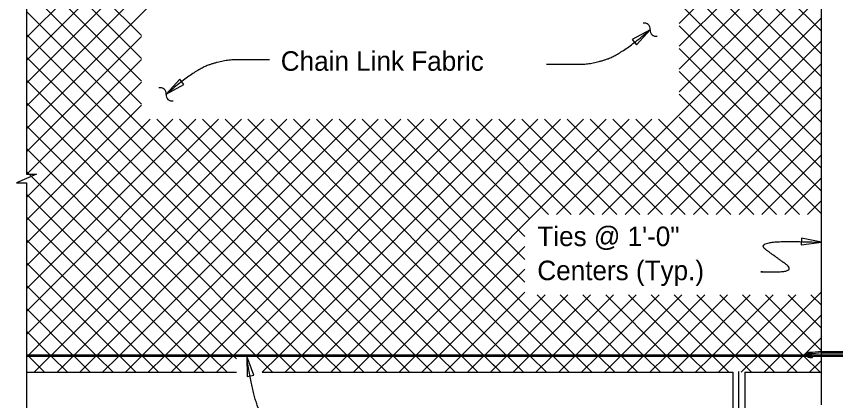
# Model space of a CAD drawing. Extents: x 0.2 to 40.8, y 0.5 to 25.7.
# Drawn here: x 16.15 to 24.62, y 16.93 to 20.9 of the extents above; entities that cross this region are included whole.
import ezdxf

# ---------------------------------------------------------------- set-up
doc = ezdxf.new("R2010")
doc.units = 0
for name, color, linetype in [('CL_Major', 7, 'Continuous'), ('Dimension', 7, 'Continuous'), ('Miscellaneous', 7, 'Continuous'), ('SteelMisc', 7, 'Continuous'), ('SteelMisc_h', 7, 'Continuous'), ('SupstrConc', 7, 'Continuous'), ('TextStructures', 7, 'Continuous')]:
    doc.layers.add(name, color=color, linetype=linetype)

msp = doc.modelspace()

# ---------------------------------------------------------------- linework, layer by layer
at = {"layer": 'CL_Major'}
msp.add_line((23.6151, 11.3358), (23.6151, 17.2313), dxfattribs=at)
at = {"layer": 'Dimension'}
for points in [[(16.252, 23.2265), (16.252, 21.2702), (16.3553, 21.2702), (16.252, 21.2252), (16.1487, 21.1802), (16.252, 21.1802), (16.252, 20.2867)], [(16.252, 20.2867), (16.252, 19.2689), (16.3553, 19.2689), (16.252, 19.2239), (16.1487, 19.1789), (16.252, 19.1789), (16.252, 16.9746)], [(16.252, 17.2246), (16.252, 15.3737), (16.3553, 15.3737), (16.252, 15.3287), (16.1487, 15.2837), (16.252, 15.2837), (16.252, 12.9339)]]:
    msp.add_lwpolyline(points, dxfattribs=at)
for points in [[(22.699, 20.7612), (22.5135, 20.6603), (22.5571, 20.6048)], [(17.695, 20.0946), (17.8805, 20.1956), (17.8369, 20.251)], [(24.4692, 18.5661), (24.2626, 18.6099), (24.2597, 18.5394)], [(18.5297, 17.3912), (18.5346, 17.18), (18.6039, 17.1934)]]:
    msp.add_lwpolyline(points, close=True, dxfattribs=at)
for centre, start, end in [((22.6394, 20.7697), 352.34263, 104.06985), ((22.7576, 20.7538), 172.34263, 284.06985), ((17.6364, 20.102), 352.34263, 104.06985), ((17.7546, 20.0861), 172.34263, 284.06985)]:
    msp.add_arc(centre, 0.0596, start, end, dxfattribs=at)
for points in [[(21.6258, 20.4048), (21.8279, 20.4048), (22.1015, 20.4048), (22.4083, 20.5127), (22.6984, 20.7617)], [(18.7638, 20.451), (18.5661, 20.451), (18.2925, 20.451), (17.9858, 20.3431), (17.6956, 20.0941)], [(23.8587, 18.2615), (23.7933, 18.2615), (24.2134, 18.2615), (23.9631, 18.4386), (23.826, 18.5413), (24.0365, 18.5838), (24.4692, 18.5661)], [(19.1927, 16.5972), (18.7949, 16.5972), (18.5909, 16.9342), (18.5297, 17.3911)]]:
    msp.add_open_spline(points, degree=2, dxfattribs=at)
at = {"layer": 'Miscellaneous'}
for p, q in [((16.252, 19.7364), (19.5586, 23.0431)), ((16.252, 20.2078), (19.0872, 23.0431)), ((16.252, 20.6792), (18.6158, 23.0431)), ((16.252, 19.9721), (19.3229, 23.0431)), ((16.252, 20.4435), (18.8515, 23.0431)), ((20.9925, 23.0431), (24.4692, 19.5664)), ((21.2282, 23.0431), (24.4692, 19.8021)), ((21.4639, 23.0431), (24.4692, 20.0378)), ((21.6996, 23.0431), (24.4692, 20.2735)), ((21.9353, 23.0431), (24.4692, 20.5092)), ((22.1711, 23.0431), (24.4692, 20.7449)), ((22.9985, 20.8261), (24.4692, 22.2968)), ((22.9985, 20.5904), (24.4692, 22.0611)), ((16.252, 21.8911), (17.4417, 20.7014)), ((22.9985, 20.3547), (24.4692, 21.8254)), ((16.252, 21.6554), (17.4417, 20.4657)), ((22.9985, 20.119), (24.4692, 21.5897)), ((16.252, 21.4197), (17.4417, 20.23)), ((21.9677, 18.8525), (24.4692, 21.354)), ((16.2232, 21.2127), (17.4417, 19.9943)), ((22.2034, 18.8525), (24.4692, 21.1183)), ((16.252, 20.9483), (19.7943, 17.4059)), ((22.4391, 18.8525), (24.4692, 20.8826)), ((22.9985, 20.8014), (24.4692, 19.3307)), ((16.252, 20.7126), (19.5586, 17.4059)), ((16.252, 19.5007), (17.4417, 20.6904)), ((22.6748, 18.8525), (24.4692, 20.6469)), ((22.9985, 20.5657), (24.4692, 19.095)), ((16.252, 20.4769), (19.3229, 17.4059)), ((16.2558, 19.2689), (17.4417, 20.4547)), ((22.9105, 18.8525), (24.4692, 20.4112)), ((22.9985, 20.33), (24.4692, 18.8593)), ((16.252, 20.2412), (19.0872, 17.4059)), ((16.252, 19.0293), (17.4417, 20.219)), ((23.1462, 18.8525), (24.4692, 20.1755)), ((22.9985, 20.0943), (24.2403, 18.8525)), ((16.252, 20.0055), (18.8515, 17.4059)), ((16.252, 18.7936), (17.4417, 19.9833)), ((23.3819, 18.8525), (24.4692, 19.9398)), ((16.252, 17.8508), (18.2378, 19.8366)), ((16.252, 18.3222), (17.7664, 19.8366)), ((16.252, 18.5579), (17.5307, 19.8366)), ((16.252, 18.0865), (18.0021, 19.8366)), ((16.252, 17.6151), (18.4735, 19.8366)), ((16.2785, 17.4059), (18.7092, 19.8366)), ((16.5142, 17.4059), (18.9449, 19.8366)), ((16.7499, 17.4059), (19.1806, 19.8366)), ((16.9856, 17.4059), (19.4163, 19.8366)), ((17.2213, 17.4059), (19.652, 19.8366)), ((17.457, 17.4059), (19.8877, 19.8366)), ((17.5994, 19.8366), (20.03, 17.4059)), ((17.6927, 17.4059), (20.1234, 19.8366)), ((17.8351, 19.8366), (20.2657, 17.4059)), ((17.9284, 17.4059), (20.3591, 19.8366)), ((18.0708, 19.8366), (20.5014, 17.4059)), ((18.1641, 17.4059), (20.5948, 19.8366)), ((18.3065, 19.8366), (20.7372, 17.4059)), ((18.3998, 17.4059), (20.8305, 19.8366)), ((18.5422, 19.8366), (21.0907, 17.2881)), ((18.6355, 17.4059), (21.0662, 19.8366)), ((18.7779, 19.8366), (21.2086, 17.4059)), ((18.8712, 17.4059), (21.3019, 19.8366)), ((19.0136, 19.8366), (21.4443, 17.4059)), ((19.1069, 17.4059), (21.5376, 19.8366)), ((19.2493, 19.8366), (21.68, 17.4059)), ((19.3426, 17.4059), (21.7733, 19.8366)), ((19.485, 19.8366), (21.9157, 17.4059)), ((19.5783, 17.4059), (22.009, 19.8366)), ((19.6962, 17.2881), (22.2447, 19.8366)), ((19.7207, 19.8366), (21.4039, 18.1533)), ((19.9564, 19.8366), (21.4039, 18.389)), ((20.0497, 17.4059), (22.4804, 19.8366)), ((20.1921, 19.8366), (21.4039, 18.6247)), ((20.4278, 19.8366), (21.4541, 18.8103)), ((20.6635, 19.8366), (21.6476, 18.8525)), ((20.8992, 19.8366), (21.8833, 18.8525)), ((21.1349, 19.8366), (22.119, 18.8525)), ((21.3706, 19.8366), (22.3547, 18.8525)), ((21.6063, 19.8366), (22.5904, 18.8525)), ((21.732, 18.8525), (22.7161, 19.8366)), ((21.842, 19.8366), (22.8261, 18.8525)), ((22.0777, 19.8366), (23.0618, 18.8525)), ((22.3134, 19.8366), (23.2975, 18.8525)), ((22.5491, 19.8366), (23.5332, 18.8525)), ((22.7848, 19.8366), (23.7689, 18.8525)), ((22.9985, 19.8586), (24.0046, 18.8525)), ((16.252, 19.7698), (18.6158, 17.4059)), ((23.6176, 18.8525), (24.4692, 19.7041)), ((16.252, 19.5341), (18.3801, 17.4059)), ((23.8533, 18.8525), (24.4692, 19.4684)), ((16.252, 19.2984), (18.1444, 17.4059)), ((24.089, 18.8525), (24.4692, 19.2327)), ((16.252, 19.0627), (17.9087, 17.4059)), ((24.3247, 18.8525), (24.4692, 18.997)), ((16.252, 18.827), (17.673, 17.4059)), ((16.252, 18.5913), (17.4373, 17.4059)), ((20.2854, 17.4059), (21.4039, 18.5244)), ((16.252, 18.3556), (17.2016, 17.4059)), ((20.5211, 17.4059), (21.4039, 18.2887)), ((16.252, 18.1198), (16.9659, 17.4059)), ((20.7568, 17.4059), (21.4039, 18.053)), ((23.821, 17.4059), (24.4692, 18.0542)), ((20.9925, 17.4059), (21.6122, 18.0255)), ((21.2282, 17.4059), (21.8479, 18.0255)), ((21.4639, 17.4059), (22.0836, 18.0255)), ((21.5318, 18.0255), (22.1514, 17.4059)), ((21.6996, 17.4059), (22.3193, 18.0255)), ((21.7675, 18.0255), (22.3871, 17.4059)), ((21.9353, 17.4059), (22.555, 18.0255)), ((22.0032, 18.0255), (22.6228, 17.4059)), ((22.1711, 17.4059), (22.7907, 18.0255)), ((22.2389, 18.0255), (22.8585, 17.4059)), ((22.4068, 17.4059), (23.0264, 18.0255)), ((22.4746, 18.0255), (23.0942, 17.4059)), ((22.6425, 17.4059), (23.2621, 18.0255)), ((22.7103, 18.0255), (23.3299, 17.4059)), ((22.8782, 17.4059), (23.4978, 18.0255)), ((22.946, 18.0255), (23.5656, 17.4059)), ((23.1139, 17.4059), (23.7335, 18.0255)), ((23.1817, 18.0255), (23.8013, 17.4059)), ((23.3496, 17.4059), (23.9692, 18.0255)), ((23.4174, 18.0255), (24.037, 17.4059)), ((23.5853, 17.4059), (24.2049, 18.0255)), ((23.6531, 18.0255), (24.2727, 17.4059)), ((23.8888, 18.0255), (24.4692, 17.4451)), ((24.1245, 18.0255), (24.4692, 17.6808)), ((24.3602, 18.0255), (24.4692, 17.9165)), ((16.252, 17.8841), (16.7302, 17.4059)), ((24.0567, 17.4059), (24.4692, 17.8185)), ((16.252, 17.6484), (16.4945, 17.4059)), ((24.3083, 17.4218), (24.4692, 17.5828)), ((16.2736, 17.3912), (16.4402, 17.2245)), ((16.3328, 17.2245), (16.4994, 17.3912)), ((16.5093, 17.3912), (16.6759, 17.2245)), ((16.5685, 17.2245), (16.7352, 17.3912)), ((16.745, 17.3912), (16.9116, 17.2245)), ((16.8042, 17.2245), (16.9709, 17.3912)), ((16.9807, 17.3912), (17.1473, 17.2245)), ((17.0399, 17.2245), (17.2066, 17.3912)), ((17.2164, 17.3912), (17.383, 17.2245)), ((17.2756, 17.2245), (17.4423, 17.3912)), ((17.4521, 17.3912), (17.6187, 17.2245)), ((17.5113, 17.2245), (17.678, 17.3912)), ((17.6878, 17.3912), (17.8544, 17.2245)), ((17.747, 17.2245), (17.9137, 17.3912)), ((17.9235, 17.3912), (18.0901, 17.2245)), ((17.9827, 17.2245), (18.1494, 17.3912)), ((18.1592, 17.3912), (18.3258, 17.2245)), ((18.2184, 17.2245), (18.3851, 17.3912)), ((18.3949, 17.3912), (18.424, 17.3621)), ((18.6306, 17.3912), (18.7972, 17.2245)), ((18.6898, 17.2245), (18.8565, 17.3912)), ((18.8663, 17.3912), (19.0329, 17.2245)), ((18.9255, 17.2245), (19.0922, 17.3912)), ((19.102, 17.3912), (19.2687, 17.2245)), ((19.1612, 17.2245), (19.3279, 17.3912)), ((19.3377, 17.3912), (19.5044, 17.2245)), ((19.3969, 17.2245), (19.5636, 17.3912)), ((19.5734, 17.3912), (19.7401, 17.2245)), ((19.6326, 17.2245), (19.7993, 17.3912)), ((19.8091, 17.3912), (19.9758, 17.2245)), ((19.8683, 17.2245), (20.035, 17.3912)), ((20.0448, 17.3912), (20.2115, 17.2245)), ((20.104, 17.2245), (20.2707, 17.3912)), ((20.2805, 17.3912), (20.4472, 17.2245)), ((20.3397, 17.2245), (20.5064, 17.3912)), ((20.5162, 17.3912), (20.6829, 17.2245)), ((20.5754, 17.2245), (20.7421, 17.3912)), ((20.7519, 17.3912), (20.9186, 17.2245)), ((20.8111, 17.2245), (20.9778, 17.3912)), ((20.9876, 17.3912), (21.1543, 17.2245)), ((21.0468, 17.2245), (21.2135, 17.3912)), ((21.2233, 17.3912), (21.39, 17.2245)), ((21.2825, 17.2245), (21.4492, 17.3912)), ((21.459, 17.3912), (21.6257, 17.2245)), ((21.5182, 17.2245), (21.6849, 17.3912)), ((21.6947, 17.3912), (21.8614, 17.2245)), ((21.7539, 17.2245), (21.9206, 17.3912)), ((21.9304, 17.3912), (22.0971, 17.2245)), ((21.9896, 17.2245), (22.1563, 17.3912)), ((22.1661, 17.3912), (22.3328, 17.2245)), ((22.2253, 17.2245), (22.392, 17.3912)), ((22.4018, 17.3912), (22.5685, 17.2245)), ((22.461, 17.2245), (22.6277, 17.3912)), ((22.6375, 17.3912), (22.8042, 17.2245)), ((22.6967, 17.2245), (22.8634, 17.3912)), ((22.8732, 17.3912), (23.0399, 17.2245)), ((22.9324, 17.2245), (23.0991, 17.3912)), ((23.1089, 17.3912), (23.2756, 17.2245)), ((23.1681, 17.2245), (23.3348, 17.3912)), ((23.3446, 17.3912), (23.5113, 17.2245)), ((23.4038, 17.2245), (23.5705, 17.3912)), ((23.5803, 17.3912), (23.747, 17.2245)), ((23.6396, 17.2245), (23.8062, 17.3912)), ((23.816, 17.3912), (23.9827, 17.2245)), ((23.8753, 17.2245), (24.0419, 17.3912)), ((24.0517, 17.3912), (24.2184, 17.2245)), ((24.111, 17.2245), (24.2776, 17.3912)), ((24.2874, 17.3912), (24.4541, 17.2245)), ((24.2924, 17.4059), (24.296, 17.4095)), ((24.3467, 17.2245), (24.4692, 17.3471))]:
    msp.add_line(p, q, dxfattribs=at)
at = {"layer": 'SteelMisc'}
for p, q in [((24.4692, 16.8894), (24.4692, 23.2644)), ((16.252, 17.4059), (24.2941, 17.4059)), ((16.252, 17.3912), (24.3207, 17.3912)), ((24.304, 17.4059), (24.3172, 17.4059)), ((24.4692, 17.4385), (24.3743, 17.4274)), ((24.4692, 17.424), (24.3766, 17.4145)), ((24.3856, 17.3912), (24.4692, 17.3912)), ((24.387, 17.4059), (24.4692, 17.4059)), ((24.4692, 17.4385), (24.7604, 17.4402)), ((24.4692, 17.424), (24.7604, 17.4257))]:
    msp.add_line(p, q, dxfattribs=at)
for centre, major_axis, ratio, start_param, end_param in [((24.3283, 17.3916), (0.0373, 0), 0.957868, 1.486836, 3.108042), ((24.3494, 17.3519), (-0.0724, 0), 0.957868, 5.162149, 5.652106), ((24.3419, 17.4036), (-0.0249, 0), 0.957868, 6.009018, 7.089857), ((24.3408, 17.4061), (0.023, 0), 0.957868, 1.29026, 2.970541), ((24.3433, 17.3996), (0.0231, 0), 0.957868, 3.779554, 4.879821), ((24.3595, 17.4007), (0.0295, 0), 0.957868, 1.220941, 4.039556), ((24.373, 17.4025), (-0.0303, -0.0108), 0.724765, 4.35367, 6.324556), ((24.3494, 17.3939), (0.0206, -0.0021), 0.798607, 4.32653, 5.220153), ((24.3629, 17.3939), (0.0206, -0.0021), 0.798607, 3.333154, 5.220153), ((24.3697, 17.3985), (-0.0139, 0), 0.957868, 5.22362, 6.905413), ((24.364, 17.3961), (-0.00795, 0), 0.957868, 6.140374, 9.314262), ((24.3781, 17.3896), (-0.0259, 0), 0.957868, 4.777514, 5.62749), ((24.3624, 17.4019), (0.0119, 0), 0.957868, 5.725876, 7.416677), ((24.3555, 17.4127), (0.0391, 0), 0.957868, 5.082588, 5.41974), ((24.3624, 17.4019), (0.0119, 0), 0.957868, 5.639684, 5.723117), ((24.3626, 17.4006), (0.0251, 0), 0.957868, 5.531357, 6.227833), ((24.3626, 17.4006), (0.0251, 0), 0.957868, 0.407687, 0.609214)]:
    msp.add_ellipse(centre, major_axis=major_axis, ratio=ratio, start_param=start_param, end_param=end_param, dxfattribs=at)
at = {"layer": 'SteelMisc_h'}
for p, q in [((24.4692, 17.4059), (24.7609, 17.4059)), ((24.4692, 17.3912), (24.7609, 17.3912))]:
    msp.add_line(p, q, dxfattribs=at)
at = {"layer": 'SupstrConc'}
for p, q in [((16.252, 17.2245), (18.424, 17.2245)), ((18.6879, 17.2245), (23.5538, 17.2245)), ((23.5538, 17.2245), (23.5538, 12.7032)), ((23.6763, 17.2245), (23.6763, 13.5578)), ((23.6763, 17.2245), (24.4692, 17.2245))]:
    msp.add_line(p, q, dxfattribs=at)

# ---------------------------------------------------------------- texts
at = {"layer": 'Dimension'}
for s, p in [('Ties @ 1\'-0" ', (21.5326, 18.5274)), ('Centers (Typ.)', (21.5326, 18.1754))]:
    msp.add_text(s, height=0.2016, dxfattribs=at).set_placement(p)
at = {"layer": 'TextStructures'}
msp.add_text('Chain Link Fabric', height=0.2016, dxfattribs=at).set_placement((18.8811, 20.3373))

doc.saveas('drawing.dxf')
